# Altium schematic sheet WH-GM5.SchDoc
size 1117 x 863 mm
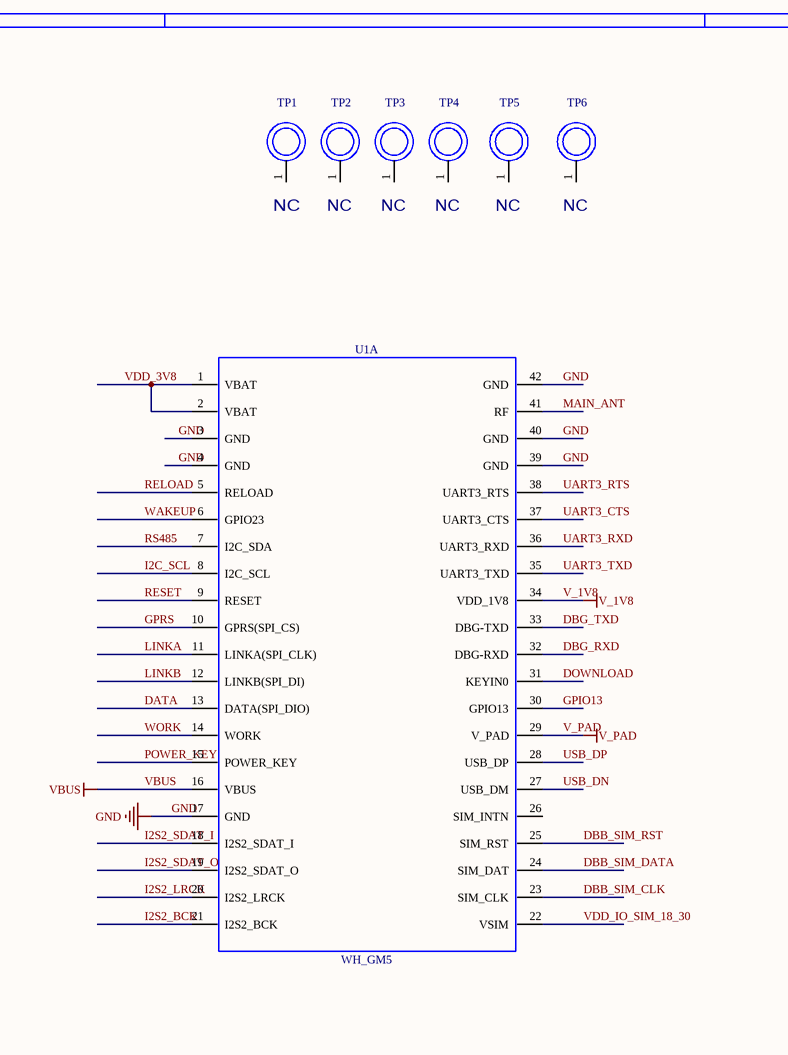
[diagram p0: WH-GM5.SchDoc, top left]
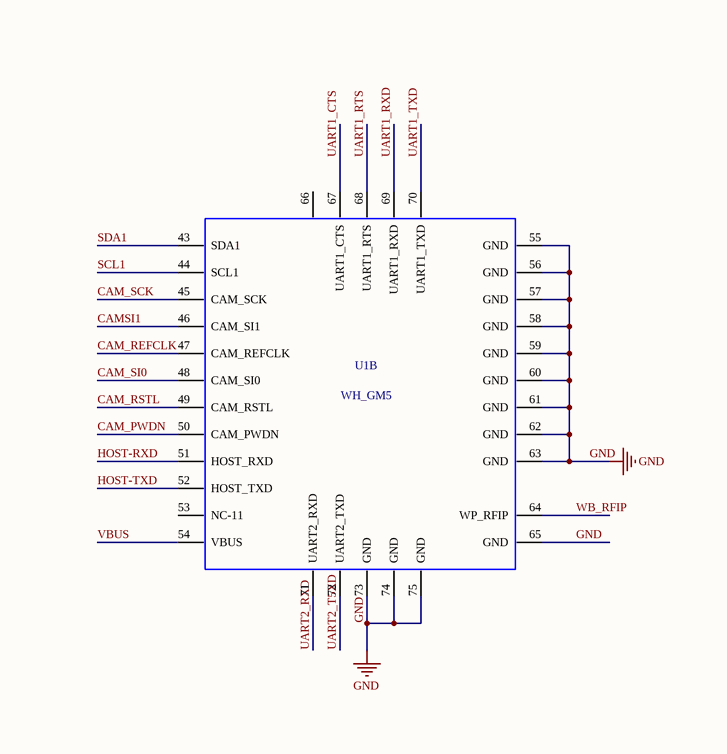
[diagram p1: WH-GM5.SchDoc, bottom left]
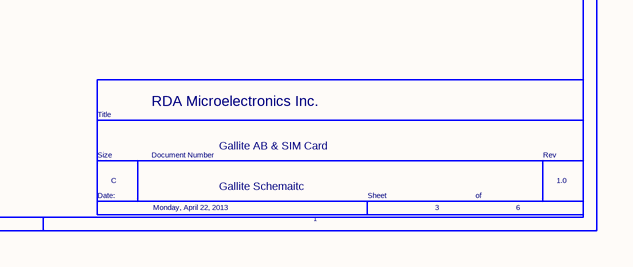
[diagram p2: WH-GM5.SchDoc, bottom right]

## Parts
TP1  TP-C150  (value not drawn)
TP2  TP-C150  (value not drawn)
TP3  TP-C150  (value not drawn)
TP4  TP-C150  (value not drawn)
TP5  TP-C150  (value not drawn)
TP6  TP-C150  (value not drawn)
U1  WH_GM5  (parts A,B of 2)

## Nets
GND: U1.3(GND) U1.4(GND) U1.17(GND) U1.39(GND) U1.40(GND) U1.42(GND) U1.55(GND) U1.56(GND) U1.57(GND) U1.58(GND) U1.59(GND) U1.60(GND) U1.61(GND) U1.62(GND) U1.63(GND) U1.65(GND) U1.73(GND) U1.74(GND) U1.75(GND)
V_1V8: U1.34(VDD_1V8)
V_PAD: U1.29(V_PAD)
VBUS: U1.16(VBUS) U1.54(VBUS)
CAM_PWDN: U1.50(CAM_PWDN)
CAM_REFCLK: U1.47(CAM_REFCLK)
CAM_RSTL: U1.49(CAM_RSTL)
CAM_SCK: U1.45(CAM_SCK)
CAM_SI0: U1.48(CAM_SI0)
CAMSI1: U1.46(CAM_SI1)
DATA: U1.13(DATA(SPI_DIO))
DBB_SIM_CLK: U1.23(SIM_CLK)
DBB_SIM_DATA: U1.24(SIM_DAT)
DBB_SIM_RST: U1.25(SIM_RST)
DBG_RXD: U1.32(DBG-RXD)
DBG_TXD: U1.33(DBG-TXD)
DOWNLOAD: U1.31(KEYIN0)
GPIO13: U1.30(GPIO13)
GPRS: U1.10(GPRS(SPI_CS))
HOST-RXD: U1.51(HOST_RXD)
HOST-TXD: U1.52(HOST_TXD)
I2C_SCL: U1.8(I2C_SCL)
I2S2_BCK: U1.21(I2S2_BCK)
I2S2_LRCK: U1.20(I2S2_LRCK)
I2S2_SDAT_I: U1.18(I2S2_SDAT_I)
I2S2_SDAT_O: U1.19(I2S2_SDAT_O)
LINKA: U1.11(LINKA(SPI_CLK))
LINKB: U1.12(LINKB(SPI_DI))
MAIN_ANT: U1.41(RF)
POWER_KEY: U1.15(POWER_KEY)
RELOAD: U1.5(RELOAD)
RESET: U1.9(RESET)
RS485: U1.7(I2C_SDA)
SCL1: U1.44(SCL1)
SDA1: U1.43(SDA1)
UART1_CTS: U1.67(UART1_CTS)
UART1_RTS: U1.68(UART1_RTS)
UART1_RXD: U1.69(UART1_RXD)
UART1_TXD: U1.70(UART1_TXD)
UART2_RXD: U1.71(UART2_RXD)
UART2_T5XD: U1.72(UART2_TXD)
UART3_CTS: U1.37(UART3_CTS)
UART3_RTS: U1.38(UART3_RTS)
UART3_RXD: U1.36(UART3_RXD)
UART3_TXD: U1.35(UART3_TXD)
USB_DN: U1.27(USB_DM)
USB_DP: U1.28(USB_DP)
VDD_3V8: U1.1(VBAT) U1.2(VBAT)
VDD_IO_SIM_18_30: U1.22(VSIM)
WAKEUP: U1.6(GPIO23)
WB_RFIP: U1.64(WP_RFIP)
WORK: U1.14(WORK)

Not connected (* = marked no-connect by the designer): TP1 1; TP2 1; TP3 1; TP4 1; TP5 1; TP6 1; U1 26(SIM_INTN) 53(NC-11) 66

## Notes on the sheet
- (near TP1) NC
- NC
- (near TP5) NC
- (near TP6) NC
- Title
- RDA Microelectronics Inc.
- Size
- Date:
- C
- Document Number
- Monday, April 22, 2013
- Gallite AB & SIM Card
- Gallite Schemaitc
- Sheet
- 3
- of
- 6
- Rev
- 1.0
- 1

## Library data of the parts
TP1-TP6 = TP-C150: test point on module D=1.5; Geometry.Height: 0.01mm; Priority: 1; Serial Number: NC; PCB DECAL: TP_C150
U1 = WH_GM5: PCB DECAL: USR_GM3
